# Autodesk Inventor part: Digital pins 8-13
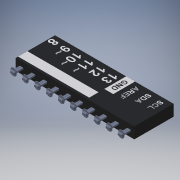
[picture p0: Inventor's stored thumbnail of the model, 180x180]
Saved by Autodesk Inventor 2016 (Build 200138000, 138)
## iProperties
Created: 2018-03
Part Number: Digital pins 8-13
Material: Générique
Document SubType Name: Modeling
Designer: Bruno
Density: 1 g/cm^3
Appearance: Par défaut
Author: Bruno
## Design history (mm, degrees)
feature "Composite1"
body "Srf1"
